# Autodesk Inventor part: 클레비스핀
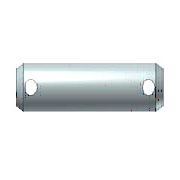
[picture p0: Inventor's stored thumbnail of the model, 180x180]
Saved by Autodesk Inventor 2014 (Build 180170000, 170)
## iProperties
IsCustomPart: 1
Created: 2012-02
Part Number: 클레비스핀
Material: 강철
Description: 머리가 없는 클레비스 핀 B
Document SubType Name: Modeling
Standard: ISO 2340
Designer: mduedu
Standard Revision: Second edition 1986-11-01
Standards Organization: ISO
Language: ko-KR
Size Designation: B - 8 x 45
Categories: <MemberInstance><Categories><Category DisplayName="조임쇠" InternalName="e4da775c-781d-43d5-af7c-5136215cf5a6" Mnemonic="FSTN"><Category DisplayName="핀" InternalNa
Density: 7.85 g/cm^3
Appearance: Steel
Author: mduedu
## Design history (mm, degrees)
sketch "스케치1"
  geometry: L1 (-4.5, 0)-(-4.5, 4); L2 (-4.5, 4)-(40.5, 4); L3 (40.5, 4)-(40.5, 0); L4 (-4.5, 0)-(40.5, 0); L5 (0, -1.46)-(0, 3.16) reference; L6 (-6.4, 0)-(18.8, 0) reference; C1 r 1 at (-1, 0); C2 r 1 at (37, 0)
  constraints: 8 end point, 2 centre point, 2 perpendicular, 2 point on line, 1 collinear, 1 parallel, 1 tangent, 1 vertical
  dimensions: "d0" = 8 diameter of L2 L4 (= NND); "d1" = 45 distance of L1.end L2.end (= NLG); "d2" = 3.5 distance from line of L1 C1.centre (= DIST1); "d3" = 3.5 distance from line of L3 C2.centre (= DIST2); "d4" = 2 diameter of C1 (= BOR1); "d5" = 2 diameter of C2 (= BOR2)
revolve "본체" stored, may be unused: angle "d7" = 90 deg
extrude "구멍1" cut sketch "스케치1" taper "d6" = 0 deg; stored distance "d8" = 10
extrude "구멍2" cut sketch "스케치1" taper "d13" = 0 deg; stored distance "d14" = 10
node "작업 평면5"
workplane "Work Plane6"
body "Solid1"
chamfer "모따기2" distance "d9" = 2 (= PHH2); stored, may be unused: angle "d10" = 30 deg (= FAWI2), second distance "d40" = 2 (= PHH2)
chamfer "모따기1" distance "d11" = 2 (= PHH1); stored, may be unused: angle "d12" = 30 deg (= FAWI1), second distance "d41" = 2 (= PHH1)
workaxis "Work Axis1"
workaxis "Work Axis2"
workplane "Work Plane1"
other parameters: "NLG" = 45 [user parameter; used in 1 equation term], "NND" = 8 [user parameter; used in 1 equation term], "PHH1" = 2 [user parameter; used in 3 equation terms], "PHH2" = 2 (= PHH1) [user parameter; used in 2 equation terms], "FAWI1" = 30 deg [user parameter; used in 1 equation term], "FAWI2" = 30 deg [user parameter; used in 1 equation term], "DIST1" = 3.5 [user parameter; used in 4 equation terms], "DIST2" = 3.5 (= DIST1) [user parameter; used in 1 equation term], "BOR1" = 2 [user parameter; used in 4 equation terms], "BOR2" = 2 (= BOR1) [user parameter; used in 1 equation term], "d15" = 0, "d42" = 0, "d43" = 0, "d44" = -4.5 (= -0.5 x BOR1 - DIST1), "d45" = -4.5 (= -0.5 x BOR1 - DIST1), "d47" = 0, "d48" = 0, "d49" = 0, "d50" = 0, "d51" = 0, "d52" = 0
